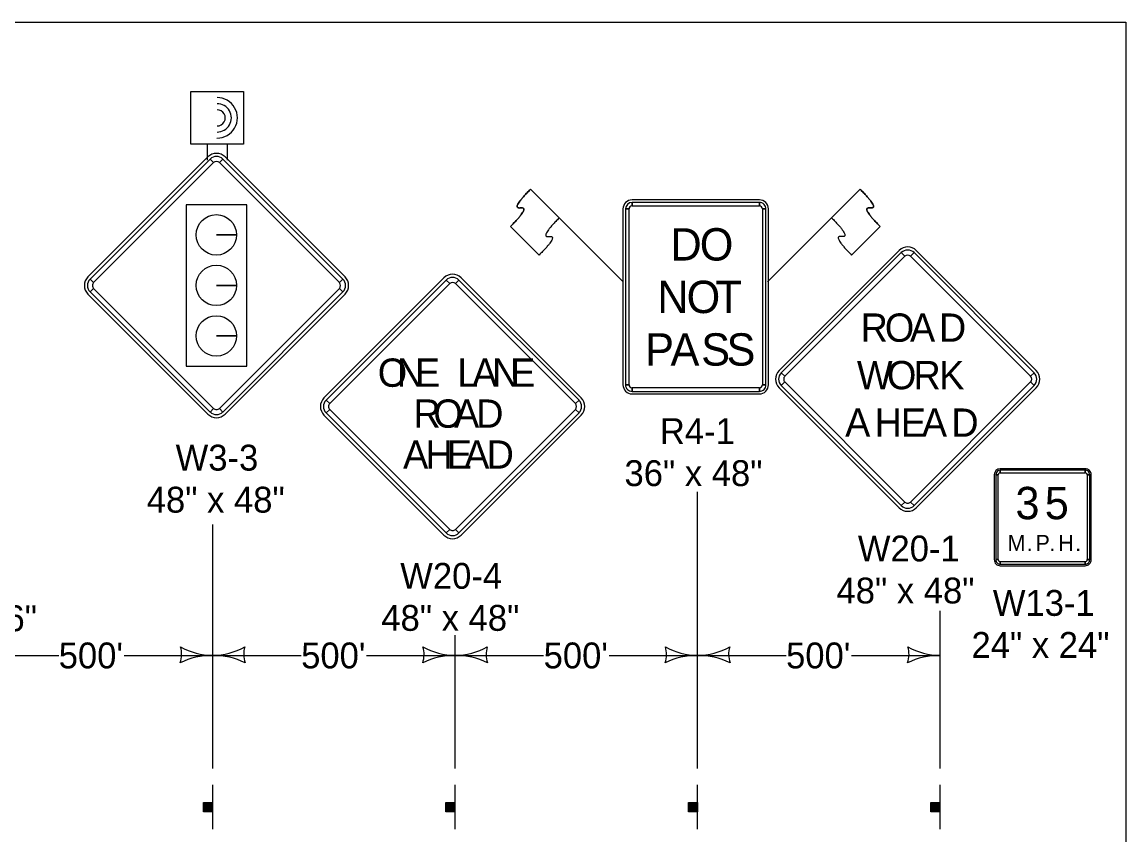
# Model space of a CAD drawing. Extents: x -2134934 to -2127057, y -2139046 to -2137036.
# Drawn here: x -2132482 to -2131799, y -2137539 to -2137036 of the extents above; entities that cross this region are included whole.
import ezdxf

# ---------------------------------------------------------------- set-up
doc = ezdxf.new("R2010")
doc.units = 0
for name, color, linetype in [('Barrier', 7, 'Continuous'), ('BridgeSuperStructureExisting', 7, 'Continuous'), ('Default', 7, 'Continuous'), ('TC_Barrier', 7, 'Continuous')]:
    doc.layers.add(name, color=color, linetype=linetype)

msp = doc.modelspace()

# ---------------------------------------------------------------- linework, layer by layer
at = {"layer": 'Barrier'}
for p, q in [((-2132367.37, -2137119.33), (-2132441.62, -2137193.57)), ((-2132366.05, -2137120.65), (-2132363.84, -2137122.86)), ((-2132360.3, -2137122.86), (-2132358.09, -2137120.65)), ((-2132282.52, -2137193.57), (-2132356.77, -2137119.33)), ((-2132110.46, -2137196.68), (-2132167.8, -2137139.38)), ((-2132167.8, -2137139.38), (-2132150.11, -2137157.06)), ((-2132021.17, -2137196.68), (-2131963.85, -2137139.36)), ((-2131963.85, -2137139.36), (-2131981.54, -2137157.04)), ((-2132026.22, -2137145.92), (-2132104.97, -2137145.92)), ((-2132104.97, -2137149.67), (-2132104.97, -2137147.48)), ((-2132026.22, -2137147.48), (-2132026.22, -2137149.67)), ((-2132110.6, -2137151.54), (-2132110.6, -2137260.29)), ((-2132109.04, -2137151.54), (-2132106.85, -2137151.54)), ((-2132024.35, -2137151.54), (-2132022.16, -2137151.54)), ((-2132020.6, -2137260.29), (-2132020.6, -2137151.54)), ((-2132162.49, -2137180.05), (-2132180.17, -2137162.37)), ((-2131969.15, -2137180.03), (-2131951.48, -2137162.35)), ((-2132349.66, -2137167.55), (-2132362.16, -2137167.55)), ((-2132362.16, -2137167.55), (-2132349.66, -2137167.55)), ((-2131939.75, -2137177.23), (-2132014, -2137251.47)), ((-2131854.9, -2137251.47), (-2131929.14, -2137177.23)), ((-2131938.42, -2137178.55), (-2131936.21, -2137180.76)), ((-2131932.68, -2137180.76), (-2131930.47, -2137178.55)), ((-2132438.08, -2137197.11), (-2132440.29, -2137194.9)), ((-2132221.34, -2137194.14), (-2132295.58, -2137268.39)), ((-2132283.85, -2137194.9), (-2132286.06, -2137197.11)), ((-2132220.01, -2137195.47), (-2132217.8, -2137197.68)), ((-2132214.27, -2137197.68), (-2132212.06, -2137195.47)), ((-2132136.48, -2137268.39), (-2132210.73, -2137194.14)), ((-2132441.62, -2137204.18), (-2132367.37, -2137278.43)), ((-2132440.29, -2137202.85), (-2132438.08, -2137200.64)), ((-2132349.66, -2137198.8), (-2132362.16, -2137198.8)), ((-2132362.16, -2137198.8), (-2132349.66, -2137198.8)), ((-2132356.77, -2137278.43), (-2132282.52, -2137204.18)), ((-2132286.06, -2137200.64), (-2132283.85, -2137202.85)), ((-2132349.66, -2137230.05), (-2132362.16, -2137230.05)), ((-2132362.16, -2137230.05), (-2132349.66, -2137230.05)), ((-2132010.46, -2137255.01), (-2132012.67, -2137252.8)), ((-2132012.67, -2137260.75), (-2132010.46, -2137258.54)), ((-2131856.22, -2137252.8), (-2131858.43, -2137255.01)), ((-2131858.43, -2137258.54), (-2131856.22, -2137260.75)), ((-2132106.85, -2137260.29), (-2132109.04, -2137260.29)), ((-2132104.97, -2137264.35), (-2132104.97, -2137262.17)), ((-2132104.97, -2137265.92), (-2132026.22, -2137265.92)), ((-2132026.22, -2137262.17), (-2132026.22, -2137264.35)), ((-2132022.16, -2137260.29), (-2132024.35, -2137260.29)), ((-2132014, -2137262.08), (-2131939.75, -2137336.33)), ((-2131929.14, -2137336.33), (-2131854.9, -2137262.08)), ((-2132292.05, -2137271.93), (-2132294.26, -2137269.72)), ((-2132137.81, -2137269.72), (-2132140.02, -2137271.93)), ((-2132363.84, -2137274.89), (-2132366.05, -2137277.1)), ((-2132358.09, -2137277.1), (-2132360.3, -2137274.89)), ((-2132295.58, -2137279), (-2132221.34, -2137353.24)), ((-2132294.26, -2137277.67), (-2132292.05, -2137275.46)), ((-2132210.73, -2137353.24), (-2132136.48, -2137279)), ((-2132140.02, -2137275.46), (-2132137.81, -2137277.67)), ((-2131824.68, -2137312.17), (-2131877.18, -2137312.17)), ((-2131877.18, -2137314.67), (-2131877.18, -2137313.1)), ((-2131824.68, -2137313.1), (-2131824.68, -2137314.67)), ((-2131880.93, -2137315.92), (-2131880.93, -2137368.42)), ((-2131879.99, -2137315.92), (-2131878.43, -2137315.92)), ((-2131823.43, -2137315.92), (-2131821.86, -2137315.92)), ((-2131820.93, -2137368.42), (-2131820.93, -2137315.92)), ((-2131936.21, -2137332.79), (-2131938.42, -2137335)), ((-2131930.47, -2137335), (-2131932.68, -2137332.79)), ((-2132217.8, -2137349.71), (-2132220.01, -2137351.92)), ((-2132212.06, -2137351.92), (-2132214.27, -2137349.71)), ((-2131878.43, -2137368.42), (-2131879.99, -2137368.42)), ((-2131821.86, -2137368.42), (-2131823.43, -2137368.42)), ((-2131877.18, -2137371.23), (-2131877.18, -2137369.67)), ((-2131877.18, -2137372.17), (-2131824.68, -2137372.17)), ((-2131824.68, -2137369.67), (-2131824.68, -2137371.23))]:
    msp.add_line(p, q, dxfattribs=at)
for points in [[(-2132366.05, -2137120.65), (-2132440.29, -2137194.9), (-2132438.08, -2137197.11), (-2132363.84, -2137122.86), (-2132366.05, -2137120.65)], [(-2132283.85, -2137194.9), (-2132358.09, -2137120.65), (-2132360.3, -2137122.86), (-2132286.06, -2137197.11), (-2132283.85, -2137194.9)], [(-2132343.34, -2137148.93), (-2132380.8, -2137148.93), (-2132380.8, -2137248.82), (-2132343.34, -2137248.82), (-2132343.34, -2137148.93)], [(-2132026.22, -2137147.48), (-2132104.97, -2137147.48), (-2132104.97, -2137149.67), (-2132026.22, -2137149.67), (-2132026.22, -2137147.48)], [(-2132109.04, -2137151.54), (-2132109.04, -2137260.29), (-2132106.85, -2137260.29), (-2132106.85, -2137151.54), (-2132109.04, -2137151.54)], [(-2132022.16, -2137260.29), (-2132022.16, -2137151.54), (-2132024.35, -2137151.54), (-2132024.35, -2137260.29), (-2132022.16, -2137260.29)], [(-2131938.42, -2137178.55), (-2132012.67, -2137252.8), (-2132010.46, -2137255.01), (-2131936.21, -2137180.76), (-2131938.42, -2137178.55)], [(-2131856.22, -2137252.8), (-2131930.47, -2137178.55), (-2131932.68, -2137180.76), (-2131858.43, -2137255.01), (-2131856.22, -2137252.8)], [(-2132220.01, -2137195.47), (-2132294.26, -2137269.72), (-2132292.05, -2137271.93), (-2132217.8, -2137197.68), (-2132220.01, -2137195.47)], [(-2132137.81, -2137269.72), (-2132212.06, -2137195.47), (-2132214.27, -2137197.68), (-2132140.02, -2137271.93), (-2132137.81, -2137269.72)], [(-2132440.29, -2137202.85), (-2132366.05, -2137277.1), (-2132363.84, -2137274.89), (-2132438.08, -2137200.64), (-2132440.29, -2137202.85)], [(-2132358.09, -2137277.1), (-2132283.85, -2137202.85), (-2132286.06, -2137200.64), (-2132360.3, -2137274.89), (-2132358.09, -2137277.1)], [(-2132012.67, -2137260.75), (-2131938.42, -2137335), (-2131936.21, -2137332.79), (-2132010.46, -2137258.54), (-2132012.67, -2137260.75)], [(-2131930.47, -2137335), (-2131856.22, -2137260.75), (-2131858.43, -2137258.54), (-2131932.68, -2137332.79), (-2131930.47, -2137335)], [(-2132104.97, -2137264.35), (-2132026.22, -2137264.35), (-2132026.22, -2137262.17), (-2132104.97, -2137262.17), (-2132104.97, -2137264.35)], [(-2132294.26, -2137277.67), (-2132220.01, -2137351.92), (-2132217.8, -2137349.71), (-2132292.05, -2137275.46), (-2132294.26, -2137277.67)], [(-2132212.06, -2137351.92), (-2132137.81, -2137277.67), (-2132140.02, -2137275.46), (-2132214.27, -2137349.71), (-2132212.06, -2137351.92)], [(-2131824.68, -2137313.1), (-2131877.18, -2137313.1), (-2131877.18, -2137314.67), (-2131824.68, -2137314.67), (-2131824.68, -2137313.1)], [(-2131879.99, -2137315.92), (-2131879.99, -2137368.42), (-2131878.43, -2137368.42), (-2131878.43, -2137315.92), (-2131879.99, -2137315.92)], [(-2131821.86, -2137368.42), (-2131821.86, -2137315.92), (-2131823.43, -2137315.92), (-2131823.43, -2137368.42), (-2131821.86, -2137368.42)], [(-2131877.18, -2137371.23), (-2131824.68, -2137371.23), (-2131824.68, -2137369.67), (-2131877.18, -2137369.67), (-2131877.18, -2137371.23)]]:
    msp.add_lwpolyline(points, close=True, dxfattribs=at)
for centre in [(-2132362.16, -2137167.55), (-2132362.16, -2137198.8), (-2132362.16, -2137230.05)]:
    msp.add_circle(centre, 12.5, dxfattribs=at)
for centre, radius, start, end in [((-2132362.07, -2137124.63), 7.5, 44.99999, 134.99974), ((-2132362.07, -2137124.63), 5.62, 44.99999, 134.99974), ((-2132362.07, -2137124.63), 2.5, 44.99999, 134.99974), ((-2132104.97, -2137151.54), 5.62, 90.00021, 179.99985), ((-2132104.97, -2137151.54), 4.06, 90.00021, 179.99985), ((-2132104.97, -2137151.54), 1.87, 90.00021, 179.99985), ((-2132026.22, -2137151.54), 5.62, 0, 90.00021), ((-2132026.22, -2137151.54), 4.06, 0, 90.00021), ((-2132026.22, -2137151.54), 1.87, 0, 90.00021), ((-2131934.45, -2137182.53), 7.5, 44.99999, 134.99974), ((-2131934.45, -2137182.53), 5.62, 44.99999, 134.99974), ((-2131934.45, -2137182.53), 2.5, 44.99999, 134.99974), ((-2132436.32, -2137198.88), 7.5, 134.99974, 224.99995), ((-2132436.32, -2137198.88), 5.62, 134.99974, 224.99995), ((-2132436.32, -2137198.88), 2.5, 134.99974, 224.99995), ((-2132287.83, -2137198.88), 2.5, 315.00016, 44.9998), ((-2132287.83, -2137198.88), 5.62, 315.00016, 44.9998), ((-2132287.83, -2137198.88), 7.5, 315.00016, 44.9998), ((-2132216.03, -2137199.45), 7.5, 44.99999, 134.99974), ((-2132216.03, -2137199.45), 5.62, 44.99999, 134.99974), ((-2132216.03, -2137199.45), 2.5, 44.99999, 134.99974), ((-2132008.69, -2137256.78), 7.5, 134.99974, 224.99995), ((-2131860.2, -2137256.78), 7.5, 315.00016, 44.9998), ((-2132008.69, -2137256.78), 5.62, 134.99974, 224.99995), ((-2132008.69, -2137256.78), 2.5, 134.99974, 224.99995), ((-2131860.2, -2137256.78), 2.5, 315.00016, 44.9998), ((-2131860.2, -2137256.78), 5.62, 315.00016, 44.9998), ((-2132104.97, -2137260.29), 5.62, 179.99985, 270.00006), ((-2132104.97, -2137260.29), 4.06, 179.99985, 270.00006), ((-2132104.97, -2137260.29), 1.87, 179.99985, 270.00006), ((-2132026.22, -2137260.29), 5.62, 270.00006, 0.00027), ((-2132026.22, -2137260.29), 4.06, 270.00006, 0.00027), ((-2132026.22, -2137260.29), 1.87, 270.00006, 0.00027), ((-2132290.28, -2137273.69), 7.5, 134.99974, 224.99995), ((-2132290.28, -2137273.69), 5.62, 134.99974, 224.99995), ((-2132290.28, -2137273.69), 2.5, 134.99974, 224.99995), ((-2132141.79, -2137273.69), 2.5, 315.00016, 44.9998), ((-2132141.79, -2137273.69), 5.62, 315.00016, 44.9998), ((-2132141.79, -2137273.69), 7.5, 315.00016, 44.9998), ((-2132362.07, -2137273.12), 7.5, 224.99995, 315.00016), ((-2132362.07, -2137273.12), 5.62, 224.99995, 315.00016), ((-2132362.07, -2137273.12), 2.5, 224.99995, 315.00016), ((-2131877.18, -2137315.92), 3.75, 90.00021, 179.99985), ((-2131877.18, -2137315.92), 2.81, 90.00021, 179.99985), ((-2131824.68, -2137315.92), 3.75, 0, 90.00021), ((-2131824.68, -2137315.92), 2.81, 0, 90.00021), ((-2131877.18, -2137315.92), 1.25, 90.00021, 179.99985), ((-2131824.68, -2137315.92), 1.25, 0, 90.00021), ((-2131934.45, -2137331.02), 2.5, 224.99995, 315.00016), ((-2131934.45, -2137331.02), 7.5, 224.99995, 315.00016), ((-2131934.45, -2137331.02), 5.62, 224.99995, 315.00016), ((-2132216.03, -2137347.94), 7.5, 224.99995, 315.00016), ((-2132216.03, -2137347.94), 5.62, 224.99995, 315.00016), ((-2132216.03, -2137347.94), 2.5, 224.99995, 315.00016), ((-2131877.18, -2137368.42), 3.75, 179.99985, 270.00006), ((-2131877.18, -2137368.42), 2.81, 179.99985, 270.00006), ((-2131877.18, -2137368.42), 1.25, 179.99985, 270.00006), ((-2131824.68, -2137368.42), 3.75, 270.00006, 0.00027), ((-2131824.68, -2137368.42), 2.81, 270.00006, 0.00027), ((-2131824.68, -2137368.42), 1.25, 270.00006, 0.00027)]:
    msp.add_arc(centre, radius, start, end, dxfattribs=at)
for points in [[(-2132180.17, -2137162.37), (-2132167.8, -2137149.99), (-2132180.17, -2137151.77), (-2132167.8, -2137139.38)], [(-2131951.48, -2137162.35), (-2131963.85, -2137149.98), (-2131951.48, -2137151.75), (-2131963.85, -2137139.36)], [(-2132150.11, -2137157.06), (-2132162.49, -2137169.44), (-2132150.12, -2137167.67), (-2132162.49, -2137180.05)], [(-2131981.54, -2137157.04), (-2131969.16, -2137169.43), (-2131981.53, -2137167.66), (-2131969.15, -2137180.03)]]:
    msp.add_open_spline(points, degree=2, dxfattribs=at)
at = {"layer": 'BridgeSuperStructureExisting'}
for p, q in [((-2132367.91, -2137111.41), (-2132367.91, -2137121.41)), ((-2132355.41, -2137111.41), (-2132355.41, -2137121.41)), ((-2132064.45, -2137497.66), (-2132064.45, -2137326.42)), ((-2132364.45, -2137497.66), (-2132364.45, -2137346.75)), ((-2131914.45, -2137497.66), (-2131914.45, -2137399.97)), ((-2132214.45, -2137497.66), (-2132214.45, -2137415.16)), ((-2132514.45, -2137427.66), (-2132459.7, -2137427.66)), ((-2132419.2, -2137427.66), (-2132364.45, -2137427.66)), ((-2132364.45, -2137427.66), (-2132309.7, -2137427.66)), ((-2132269.2, -2137427.66), (-2132214.45, -2137427.66)), ((-2132214.45, -2137427.66), (-2132159.7, -2137427.66)), ((-2132119.2, -2137427.66), (-2132064.45, -2137427.66)), ((-2132064.45, -2137427.66), (-2132009.7, -2137427.66)), ((-2131969.2, -2137427.66), (-2131914.45, -2137427.66)), ((-2132364.45, -2137535.16), (-2132364.45, -2137507.66)), ((-2132214.45, -2137535.16), (-2132214.45, -2137507.66)), ((-2132064.45, -2137535.16), (-2132064.45, -2137507.66)), ((-2131914.45, -2137535.16), (-2131914.45, -2137507.66)), ((-2132369.77, -2137524.3), (-2132369.77, -2137518.71)), ((-2132369.45, -2137518.71), (-2132369.45, -2137524.3)), ((-2132369.23, -2137524.3), (-2132369.23, -2137518.71)), ((-2132368.91, -2137518.71), (-2132368.91, -2137524.3)), ((-2132368.68, -2137524.3), (-2132368.7, -2137518.71)), ((-2132368.27, -2137518.71), (-2132368.25, -2137524.3)), ((-2132368.05, -2137524.3), (-2132368.05, -2137518.71)), ((-2132367.62, -2137518.71), (-2132367.62, -2137524.3)), ((-2132367.24, -2137524.3), (-2132367.24, -2137518.71)), ((-2132366.92, -2137518.71), (-2132366.9, -2137524.3)), ((-2132366.7, -2137524.3), (-2132366.7, -2137518.71)), ((-2132366.43, -2137518.71), (-2132366.43, -2137524.3)), ((-2132366.1, -2137524.3), (-2132366.1, -2137518.71)), ((-2132365.89, -2137518.71), (-2132365.89, -2137524.3)), ((-2132365.67, -2137524.3), (-2132365.67, -2137518.71)), ((-2132365.4, -2137518.71), (-2132365.4, -2137524.3)), ((-2132365.14, -2137524.3), (-2132365.14, -2137518.71)), ((-2132364.86, -2137518.71), (-2132364.86, -2137524.3)), ((-2132219.77, -2137524.3), (-2132219.77, -2137518.71)), ((-2132219.45, -2137518.71), (-2132219.45, -2137524.3)), ((-2132219.23, -2137524.3), (-2132219.23, -2137518.71)), ((-2132218.91, -2137518.71), (-2132218.91, -2137524.3)), ((-2132218.69, -2137524.3), (-2132218.7, -2137518.71)), ((-2132218.27, -2137518.71), (-2132218.25, -2137524.3)), ((-2132218.05, -2137524.3), (-2132218.05, -2137518.71)), ((-2132217.62, -2137518.71), (-2132217.62, -2137524.3)), ((-2132217.24, -2137524.3), (-2132217.24, -2137518.71)), ((-2132216.92, -2137518.71), (-2132216.9, -2137524.3)), ((-2132216.7, -2137524.3), (-2132216.7, -2137518.71)), ((-2132216.43, -2137518.71), (-2132216.43, -2137524.3)), ((-2132216.1, -2137524.3), (-2132216.1, -2137518.71)), ((-2132215.89, -2137518.71), (-2132215.89, -2137524.3)), ((-2132215.67, -2137524.3), (-2132215.67, -2137518.71)), ((-2132215.4, -2137518.71), (-2132215.4, -2137524.3)), ((-2132215.14, -2137524.3), (-2132215.14, -2137518.71)), ((-2132214.86, -2137518.71), (-2132214.86, -2137524.3)), ((-2132069.77, -2137524.3), (-2132069.77, -2137518.71)), ((-2132069.45, -2137518.71), (-2132069.45, -2137524.3)), ((-2132069.23, -2137524.3), (-2132069.23, -2137518.71)), ((-2132068.91, -2137518.71), (-2132068.91, -2137524.3)), ((-2132068.69, -2137524.3), (-2132068.7, -2137518.71)), ((-2132068.27, -2137518.71), (-2132068.25, -2137524.3)), ((-2132068.05, -2137524.3), (-2132068.05, -2137518.71)), ((-2132067.62, -2137518.71), (-2132067.62, -2137524.3)), ((-2132067.24, -2137524.3), (-2132067.24, -2137518.71)), ((-2132066.92, -2137518.71), (-2132066.9, -2137524.3)), ((-2132066.7, -2137524.3), (-2132066.7, -2137518.71)), ((-2132066.43, -2137518.71), (-2132066.43, -2137524.3)), ((-2132066.1, -2137524.3), (-2132066.1, -2137518.71)), ((-2132065.89, -2137518.71), (-2132065.89, -2137524.3)), ((-2132065.67, -2137524.3), (-2132065.67, -2137518.71)), ((-2132065.4, -2137518.71), (-2132065.4, -2137524.3)), ((-2132065.14, -2137524.3), (-2132065.14, -2137518.71)), ((-2132064.86, -2137518.71), (-2132064.86, -2137524.3)), ((-2131919.77, -2137524.3), (-2131919.77, -2137518.71)), ((-2131919.45, -2137518.71), (-2131919.45, -2137524.3)), ((-2131919.23, -2137524.3), (-2131919.23, -2137518.71)), ((-2131918.91, -2137518.71), (-2131918.91, -2137524.3)), ((-2131918.69, -2137524.3), (-2131918.7, -2137518.71)), ((-2131918.27, -2137518.71), (-2131918.25, -2137524.3)), ((-2131918.05, -2137524.3), (-2131918.05, -2137518.71)), ((-2131917.62, -2137518.71), (-2131917.62, -2137524.3)), ((-2131917.24, -2137524.3), (-2131917.24, -2137518.71)), ((-2131916.92, -2137518.71), (-2131916.9, -2137524.3)), ((-2131916.7, -2137524.3), (-2131916.7, -2137518.71)), ((-2131916.43, -2137518.71), (-2131916.43, -2137524.3)), ((-2131916.1, -2137524.3), (-2131916.1, -2137518.71)), ((-2131915.89, -2137518.71), (-2131915.89, -2137524.3)), ((-2131915.67, -2137524.3), (-2131915.67, -2137518.71)), ((-2131915.4, -2137518.71), (-2131915.4, -2137524.3)), ((-2131915.14, -2137524.3), (-2131915.14, -2137518.71)), ((-2131914.86, -2137518.71), (-2131914.86, -2137524.3))]:
    msp.add_line(p, q, dxfattribs=at)
for points in [[(-2132377.91, -2137111.41), (-2132377.91, -2137078.91), (-2132345.41, -2137078.91), (-2132345.41, -2137111.41)], [(-2132364.54, -2137518.71), (-2132364.54, -2137524.34), (-2132370.17, -2137524.34), (-2132370.17, -2137518.71)], [(-2132214.54, -2137518.71), (-2132214.54, -2137524.34), (-2132220.17, -2137524.34), (-2132220.17, -2137518.71)], [(-2132064.54, -2137518.71), (-2132064.54, -2137524.34), (-2132070.17, -2137524.34), (-2132070.17, -2137518.71)], [(-2131914.54, -2137518.71), (-2131914.54, -2137524.34), (-2131920.17, -2137524.34), (-2131920.17, -2137518.71)]]:
    msp.add_lwpolyline(points, close=True, dxfattribs=at)
for centre, radius, start, end in [((-2132361.65, -2137095.18), 12.5, 269.40414, 90.54446), ((-2132361.65, -2137095.18), 12.5, 269.40414, 90.54446), ((-2132361.65, -2137095.18), 8.75, 269.40414, 90.54446), ((-2132361.65, -2137095.18), 5, 269.40414, 90.54446), ((-2132400.06, -2137427.04), 16.42, 341.26665, 16.73335), ((-2132363.69, -2137385.17), 42.5, 240.92751, 268.9824), ((-2132365.2, -2137385.17), 42.5, 271.0176, 299.07249), ((-2132328.83, -2137427.04), 16.42, 163.26665, 198.73335), ((-2132250.06, -2137427.04), 16.42, 341.26665, 16.73335), ((-2132213.69, -2137385.17), 42.5, 240.92751, 268.9824), ((-2132215.2, -2137385.17), 42.5, 271.0176, 299.07249), ((-2132178.83, -2137427.04), 16.42, 163.26665, 198.73335), ((-2132100.06, -2137427.04), 16.42, 341.26665, 16.73335), ((-2132063.69, -2137385.17), 42.5, 240.92751, 268.9824), ((-2132065.2, -2137385.17), 42.5, 271.0176, 299.07249), ((-2132028.83, -2137427.04), 16.42, 163.26665, 198.73335), ((-2131950.06, -2137427.04), 16.42, 341.26665, 16.73335), ((-2131913.69, -2137385.17), 42.5, 240.92751, 268.9824), ((-2132365.17, -2137470.15), 42.5, 89.0176, 117.07249), ((-2132363.72, -2137470.15), 42.5, 62.92751, 90.9824), ((-2132215.17, -2137470.15), 42.5, 89.0176, 117.07249), ((-2132213.72, -2137470.15), 42.5, 62.92751, 90.9824), ((-2132065.18, -2137470.15), 42.5, 89.0176, 117.07249), ((-2132063.72, -2137470.15), 42.5, 62.92751, 90.9824), ((-2131915.18, -2137470.15), 42.5, 89.0176, 117.07249)]:
    msp.add_arc(centre, radius, start, end, dxfattribs=at)
at = {"layer": 'Default'}
msp.add_lwpolyline([(-2134934.44, -2137035.95), (-2131799.45, -2137035.95), (-2131799.45, -2139045.94), (-2134934.44, -2139045.94)], close=True, dxfattribs=at)
at = {"layer": 'TC_Barrier'}
for p, q in [((-2132180.17, -2137162.37), (-2132162.49, -2137180.05)), ((-2131951.48, -2137162.35), (-2131969.15, -2137180.03))]:
    msp.add_line(p, q, dxfattribs=at)
for points in [[(-2132167.8, -2137139.38), (-2132180.17, -2137151.77), (-2132167.8, -2137149.99), (-2132180.17, -2137162.37)], [(-2131963.85, -2137139.36), (-2131951.48, -2137151.75), (-2131963.85, -2137149.98), (-2131951.48, -2137162.35)], [(-2132150.11, -2137157.06), (-2132162.49, -2137169.44), (-2132150.12, -2137167.67), (-2132162.49, -2137180.05)], [(-2131981.54, -2137157.04), (-2131969.16, -2137169.43), (-2131981.53, -2137167.66), (-2131969.15, -2137180.03)]]:
    msp.add_open_spline(points, degree=2, dxfattribs=at)

# ---------------------------------------------------------------- texts
at = {"layer": 'Barrier'}
for s, height, p in [('D', 20, (-2132081.22, -2137183.42)), ('O', 20, (-2132063.1, -2137183.42)), ('N', 20, (-2132089.35, -2137215.92)), ('O', 20, (-2132071.22, -2137215.92)), ('T', 20, (-2132053.41, -2137215.92)), ('R', 17.5, (-2131963.61, -2137233.65)), ('O', 17.5, (-2131948.6, -2137233.65)), ('A', 17.5, (-2131933.05, -2137233.65)), ('D', 17.5, (-2131915.17, -2137233.65)), ('P', 20, (-2132096.86, -2137248.42)), ('A', 20, (-2132081.18, -2137248.42)), ('S', 20, (-2132062.21, -2137248.42)), ('S', 20, (-2132046.52, -2137248.42)), ('O', 17.5, (-2132262.32, -2137261.51)), ('N', 17.5, (-2132250.54, -2137261.51)), ('E', 17.5, (-2132239.32, -2137261.51)), ('L', 17.5, (-2132213.07, -2137261.51)), ('A', 17.5, (-2132203.87, -2137261.51)), ('N', 17.5, (-2132191.6, -2137261.51)), ('E', 17.5, (-2132180.37, -2137261.51)), ('W', 17.5, (-2131965.89, -2137263.03)), ('O', 17.5, (-2131947.3, -2137263.03)), ('R', 17.5, (-2131930.89, -2137263.03)), ('K', 17.5, (-2131915.03, -2137263.03)), ('R', 17.5, (-2132240.21, -2137286.82)), ('O', 17.5, (-2132227.92, -2137286.82)), ('A', 17.5, (-2132215.08, -2137286.82)), ('D', 17.5, (-2132201.43, -2137286.82)), ('A', 17.5, (-2131973.17, -2137292.4)), ('H', 17.5, (-2131954.96, -2137292.4)), ('E', 17.5, (-2131938.73, -2137292.4)), ('A', 17.5, (-2131925.69, -2137292.4)), ('D', 17.5, (-2131907.48, -2137292.4)), ('R4-1', 16, (-2132087.76, -2137296.92)), ('W3-3', 16, (-2132387.36, -2137313.34)), ('A', 17.5, (-2132246.65, -2137312.13)), ('H', 17.5, (-2132232.78, -2137312.13)), ('E', 17.5, (-2132219.57, -2137312.13)), ('A', 17.5, (-2132208.85, -2137312.13)), ('D', 17.5, (-2132194.99, -2137312.13)), ('36" x 48"', 16, (-2132109.67, -2137322.92)), ('48" x 48"', 16, (-2132405.24, -2137339.34)), ('3', 20, (-2131867.78, -2137343.41)), ('5', 20, (-2131849.65, -2137343.41)), ('W20-1', 16, (-2131965.3, -2137369.52)), ('M', 10, (-2131872.7, -2137363.1)), ('P', 10, (-2131855.45, -2137363.1)), ('H', 10, (-2131841.33, -2137363.1)), ('.', 10, (-2131860.91, -2137363.1)), ('.', 10, (-2131846.79, -2137363.1)), ('.', 10, (-2131830.86, -2137363.1)), ('W20-4', 16, (-2132248.4, -2137386.44)), ('48" x 48"', 16, (-2131978.51, -2137395.52)), ('W13-1', 16, (-2131881.78, -2137403.17)), ('24" x 36"', 16, (-2132558.51, -2137412.66)), ('48" x 48"', 16, (-2132260.1, -2137412.44)), ('24" x 24"', 16, (-2131894.99, -2137429.17))]:
    msp.add_text(s, height=height, dxfattribs=at).set_placement(p)
at = {"layer": 'BridgeSuperStructureExisting'}
for p in [(-2132459.7, -2137435.66), (-2132309.7, -2137435.66), (-2132159.7, -2137435.66), (-2132009.7, -2137435.66)]:
    msp.add_text("500'", height=16, dxfattribs=at).set_placement(p)

doc.saveas('drawing.dxf')
